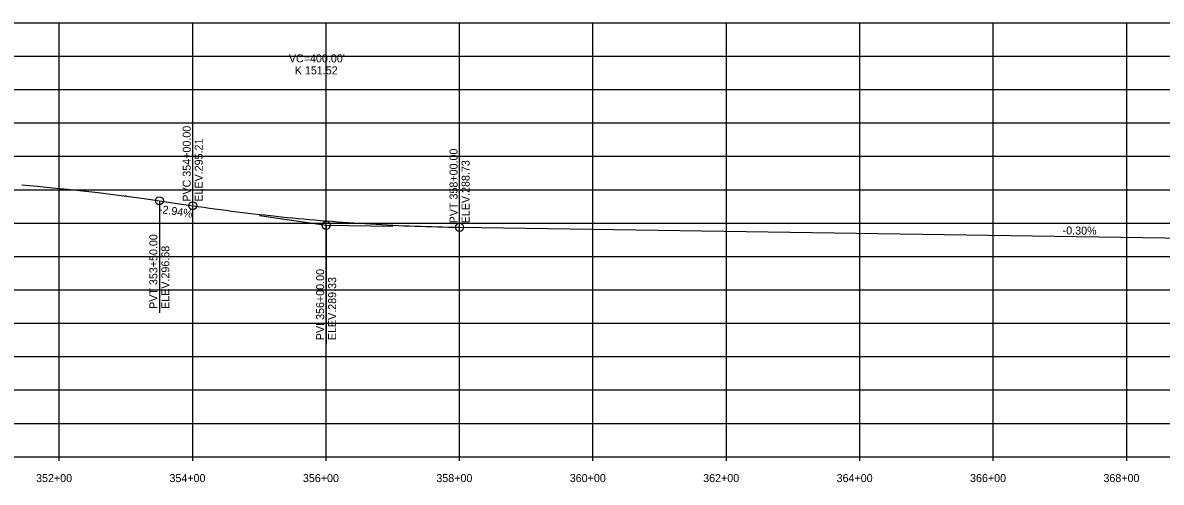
# Model space of a CAD drawing. Extents: x 880555 to 887700, y 1561392 to 1563161.
# Drawn here: x 884376 to 886082, y 1562454 to 1563143 of the extents above; entities that cross this region are included whole.
import ezdxf

# ---------------------------------------------------------------- set-up
doc = ezdxf.new("R2010")
doc.units = 0
for name, color, linetype in [('1', 7, 'Continuous'), ('30', 7, 'Continuous'), ('37', 7, 'Continuous'), ('56', 7, 'Continuous'), ('R_Axis', 7, 'Continuous')]:
    doc.layers.add(name, color=color, linetype=linetype)

msp = doc.modelspace()

# ---------------------------------------------------------------- linework, layer by layer
at = {"layer": '1'}
for p, q in [((884730.6, 1562853.9), (884830.6, 1562839.2)), ((884830.6, 1562839.2), (884930.6, 1562837.7))]:
    msp.add_line(p, q, dxfattribs=at)
at = {"layer": '37'}
for p, q in [((880630.6, 1563142.6), (887630.6, 1563142.6)), ((880630.6, 1563142.6), (887630.6, 1563142.6)), ((884430.6, 1562492.6), (884430.6, 1563142.6)), ((884630.6, 1562492.6), (884630.6, 1563142.6)), ((884830.6, 1562492.6), (884830.6, 1563142.6)), ((885030.6, 1562492.6), (885030.6, 1563142.6)), ((885230.6, 1562492.6), (885230.6, 1563142.6)), ((885430.6, 1562492.6), (885430.6, 1563142.6)), ((885630.6, 1562492.6), (885630.6, 1563142.6)), ((885830.6, 1562492.6), (885830.6, 1563142.6)), ((886030.6, 1562492.6), (886030.6, 1563142.6)), ((880630.6, 1563092.6), (887630.6, 1563092.6)), ((880630.6, 1563042.6), (887630.6, 1563042.6)), ((880630.6, 1562992.6), (887630.6, 1562992.6)), ((880630.6, 1562942.6), (887630.6, 1562942.6)), ((880630.6, 1562892.6), (887630.6, 1562892.6)), ((880630.6, 1562842.6), (887630.6, 1562842.6)), ((880630.6, 1562792.6), (887630.6, 1562792.6)), ((880630.6, 1562742.6), (887630.6, 1562742.6)), ((880630.6, 1562692.6), (887630.6, 1562692.6)), ((880630.6, 1562642.6), (887630.6, 1562642.6)), ((880630.6, 1562592.6), (887630.6, 1562592.6)), ((880630.6, 1562542.6), (887630.6, 1562542.6)), ((880630.6, 1562492.6), (887630.6, 1562492.6)), ((884430.6, 1562486.6), (884430.6, 1562492.6)), ((884630.6, 1562486.6), (884630.6, 1562492.6)), ((884830.6, 1562486.6), (884830.6, 1562492.6)), ((885030.6, 1562486.6), (885030.6, 1562492.6)), ((885230.6, 1562486.6), (885230.6, 1562492.6)), ((885430.6, 1562486.6), (885430.6, 1562492.6)), ((885630.6, 1562486.6), (885630.6, 1562492.6)), ((885830.6, 1562486.6), (885830.6, 1562492.6)), ((886030.6, 1562486.6), (886030.6, 1562492.6))]:
    msp.add_line(p, q, dxfattribs=at)
at = {"layer": '56'}
for p, q in [((884630.6, 1562868.6), (884630.6, 1563036.6)), ((885030.6, 1562836.2), (885030.6, 1563004.2)), ((884580.6, 1562876), (884580.6, 1562708)), ((884580.6, 1562876), (884630.6, 1562868.6)), ((884830.6, 1562839.2), (884830.6, 1562829.2)), ((884830.6, 1562829.2), (884830.6, 1562661.2)), ((885030.6, 1562836.2), (886905.6, 1562808.1))]:
    msp.add_line(p, q, dxfattribs=at)
for points in [[(884374.4, 1562899.7), (884397.3, 1562897.7), (884420.2, 1562895.6), (884443.1, 1562893.3), (884466, 1562890.8), (884488.9, 1562888.2), (884511.9, 1562885.4), (884534.8, 1562882.4), (884557.7, 1562879.3), (884580.6, 1562876)], [(884630.6, 1562868.6), (884638.9, 1562867.4), (884647.3, 1562866.2), (884655.6, 1562865.1), (884663.9, 1562863.9), (884672.3, 1562862.8), (884680.6, 1562861.7), (884688.9, 1562860.6), (884697.3, 1562859.6), (884705.6, 1562858.5), (884713.9, 1562857.5), (884722.3, 1562856.6), (884730.6, 1562855.6), (884738.9, 1562854.7), (884747.3, 1562853.7), (884755.6, 1562852.8), (884763.9, 1562852), (884772.3, 1562851.1), (884780.6, 1562850.3), (884788.9, 1562849.5), (884797.3, 1562848.7), (884805.6, 1562848), (884813.9, 1562847.2), (884822.3, 1562846.5), (884838.9, 1562845.2), (884847.3, 1562844.5), (884855.6, 1562843.9), (884863.9, 1562843.3), (884872.3, 1562842.8), (884880.6, 1562842.2), (884888.9, 1562841.7), (884897.3, 1562841.2), (884905.6, 1562840.7), (884913.9, 1562840.2), (884922.3, 1562839.8), (884930.6, 1562839.4), (884938.9, 1562839), (884947.3, 1562838.6), (884955.6, 1562838.3), (884963.9, 1562838), (884972.3, 1562837.7), (884980.6, 1562837.4), (884988.9, 1562837.2), (884997.3, 1562836.9), (885005.6, 1562836.7), (885013.9, 1562836.5), (885022.3, 1562836.4), (885030.6, 1562836.2)]]:
    msp.add_lwpolyline(points, dxfattribs=at)
for centre in [(884580.6, 1562876), (884630.6, 1562868.6), (884830.6, 1562839.2), (885030.6, 1562836.2)]:
    msp.add_circle(centre, 6, dxfattribs=at)
at = {"layer": 'R_Axis'}
msp.add_line((884530.6, 1562883.7), (884530.6, 1562884.6), dxfattribs=at)

# ---------------------------------------------------------------- texts
at = {"layer": '30'}
for s, p in [('352+00', (884395.8, 1562454.6)), ('354+00', (884595.8, 1562454.6)), ('356+00', (884795.8, 1562454.6)), ('358+00', (884995.8, 1562454.6)), ('360+00', (885195.8, 1562454.6)), ('362+00', (885395.8, 1562454.6)), ('364+00', (885595.8, 1562454.6)), ('366+00', (885795.8, 1562454.6)), ('368+00', (885995.8, 1562454.6))]:
    msp.add_text(s, height=12, dxfattribs=at).set_placement(p)
at = {"layer": '56'}
for s, p in [("VC=400.00'", (884774.8, 1563083.3)), ('K 151.52', (884783.6, 1563065.3))]:
    msp.add_text(s, height=12, dxfattribs=at).set_placement(p)
for s, rotation, p in [('PVC 354+00.00', 90, (884627.6, 1562874.6)), ('ELEV.295.21', 90, (884645.6, 1562874.6)), ('PVT 358+00.00', 90, (885027.6, 1562842.2)), ('ELEV.288.73', 90, (885045.6, 1562842.2)), ('-2.94%', 351.6374, (884579.3, 1562857.9)), ('-0.30%', 359.1406, (885934.6, 1562825.7)), ('PVT 353+50.00', 90, (884577.6, 1562714)), ('ELEV.296.68', 90, (884595.6, 1562714)), ('PVI 356+00.00', 90, (884827.6, 1562667.2)), ('ELEV.289.33', 90, (884845.6, 1562667.2))]:
    msp.add_text(s, height=12, rotation=rotation, dxfattribs=at).set_placement(p)

doc.saveas('drawing.dxf')
